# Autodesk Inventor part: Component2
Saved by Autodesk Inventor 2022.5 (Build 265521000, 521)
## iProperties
Created: 2024-12
Part Number: Component2
Material: Generic
Document SubType Name: Modeling
Designer: AdminForWorker
Density: 1 g/cm^3
Appearance: Default
Title: Component2
Author: AdminForWorker
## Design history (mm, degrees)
feature "Body4"
feature "Body1"
feature "Body3"
feature "Body2"
body "Solid1"
body "Solid2"
body "Solid3"
body "Solid4"
